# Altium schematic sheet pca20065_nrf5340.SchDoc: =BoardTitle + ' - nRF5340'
size A3; Organization: Nordic Semiconductor; DocumentNumber: 3; SheetNumber: 3; SheetTotal: 10; CompanyName: Nordic Semiconductor; DocumentSize: A3
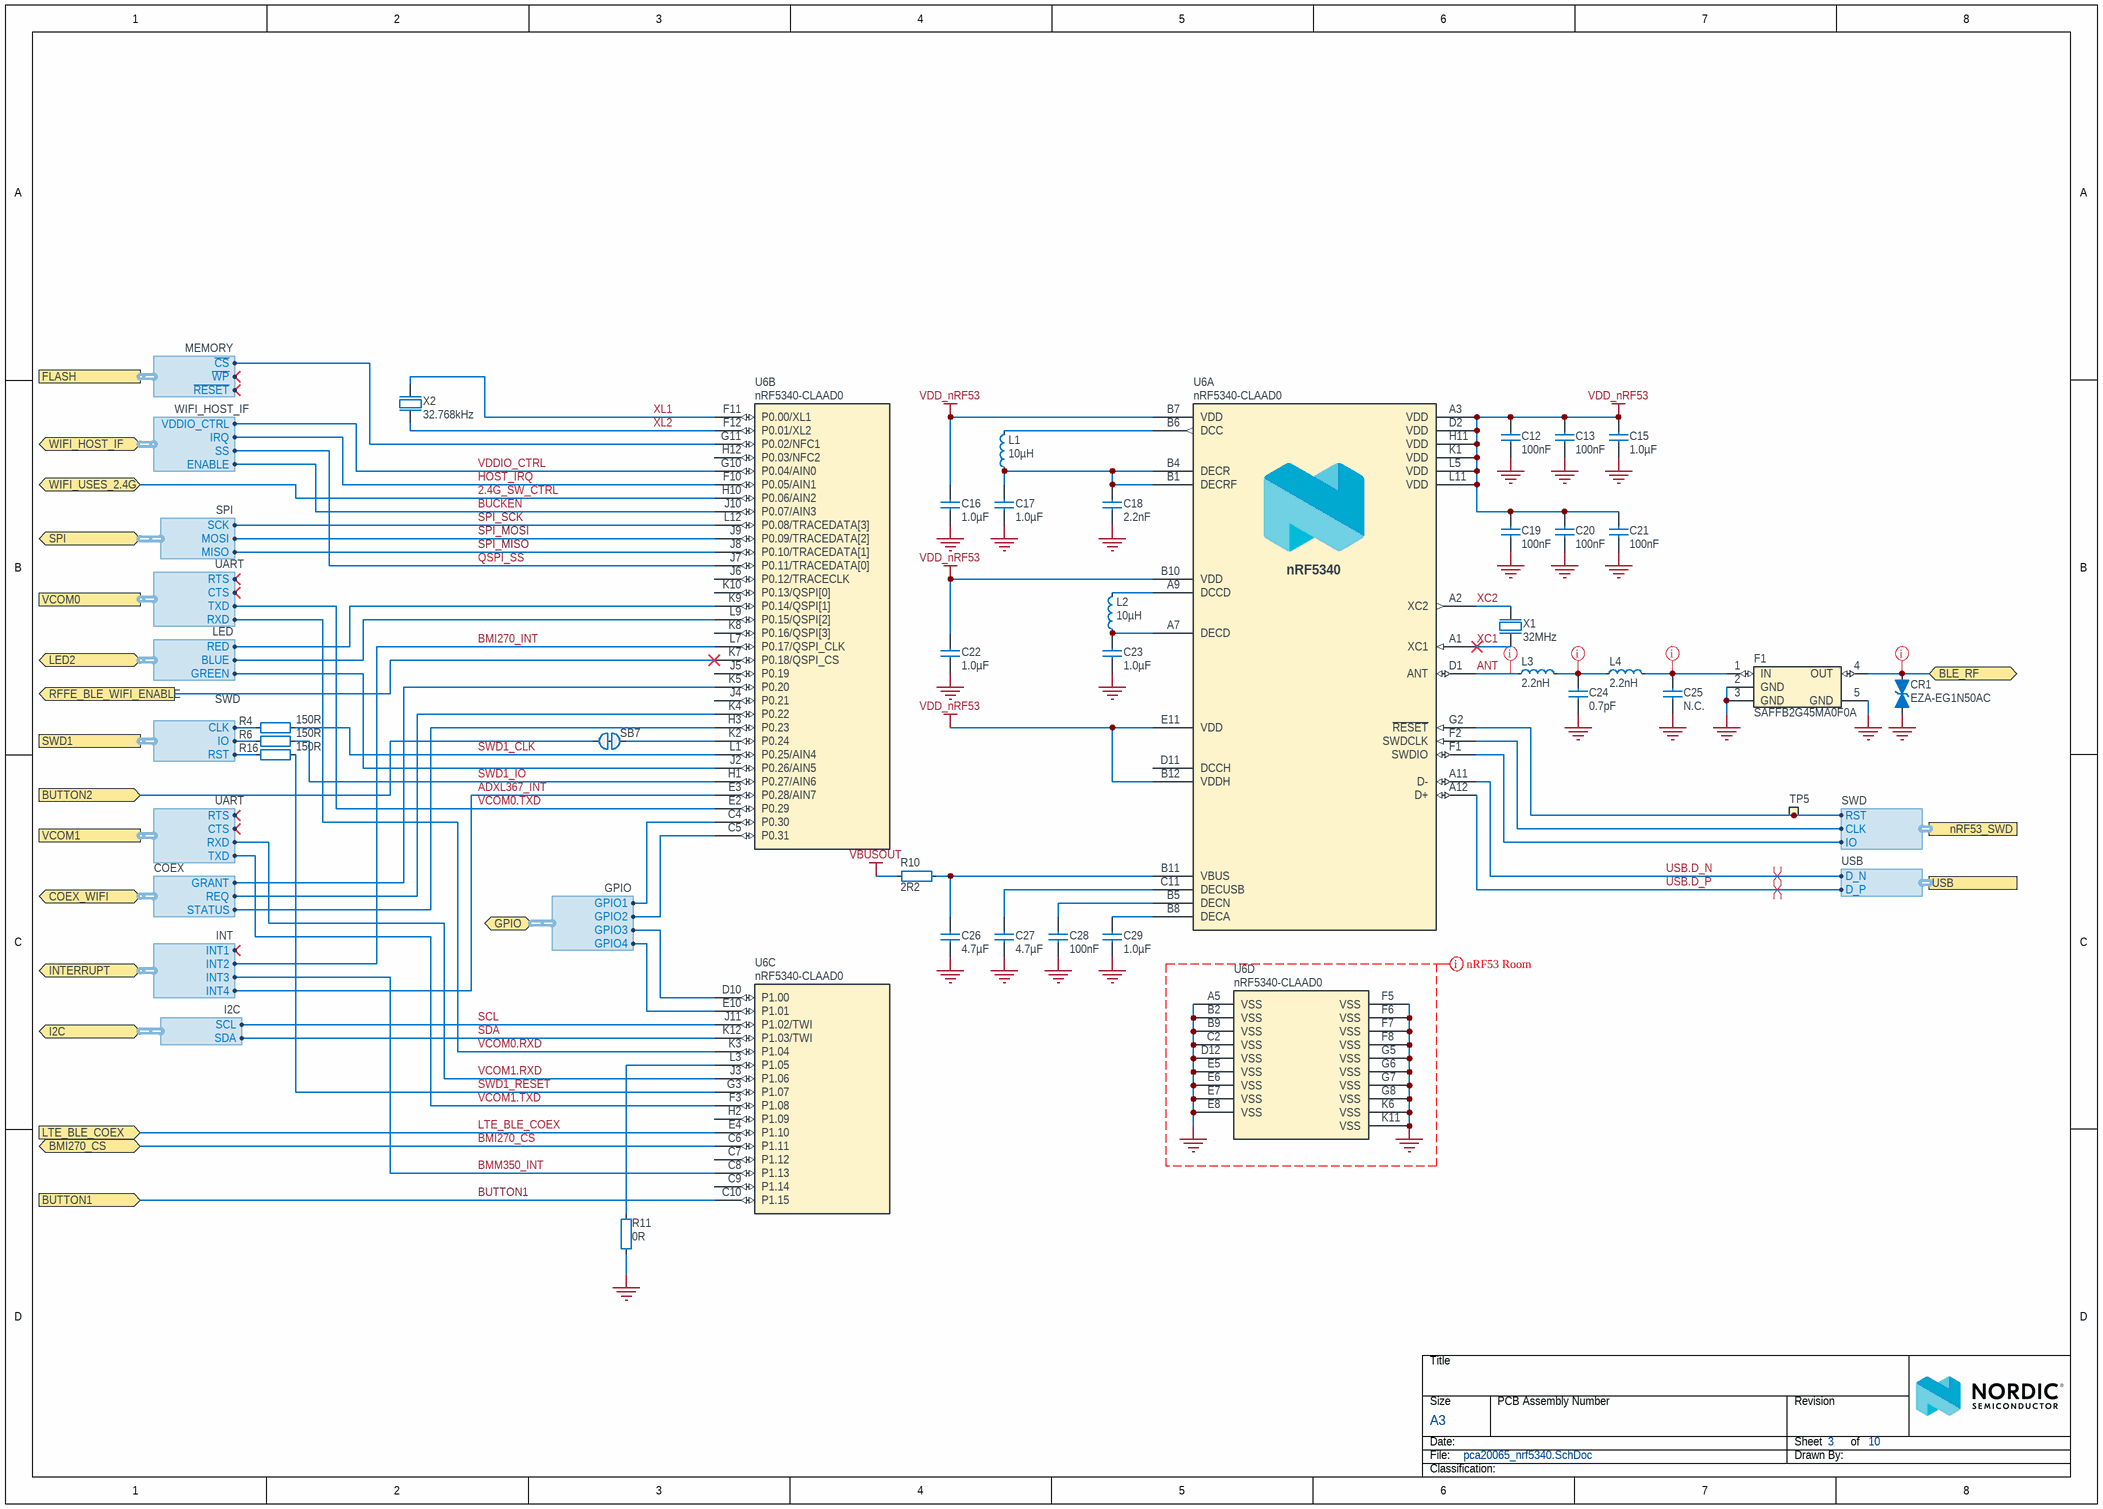
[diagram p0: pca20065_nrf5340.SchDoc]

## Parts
C12  100nF  [CAPC0603X03L_C]
C13  100nF  [CAPC0603X03L_C]
C15  1.0µF  [CAPC1005X04L]
C16  1.0µF  [CAPC1005X04L]
C17  1.0µF  [CAPC1005X04L]
C18  2.2nF  [CAPC0603X03L_C]
C19  100nF  [CAPC0603X03L_C]
C20  100nF  [CAPC0603X03L_C]
C21  100nF  [CAPC0603X03L_C]
C22  1.0µF  [CAPC1005X04L]
C23  1.0µF  [CAPC1005X04L]
C24  0.7pF  [CAPC0603X03L_C]
C25  N.C.  [CAPC0603X03L_C_NC]
C26  4.7µF  [CAPC1608X06L]
C27  4.7µF  [CAPC1608X06L]
C28  100nF  [CAPC0603X03L_C]
C29  1.0µF  [CAPC1005X04L]
CR1  EZA-EG1N50AC  [RESC0603X03L_C]
F1  SAFFB2G45MA0F0A  [SAFFB2G45MA0F0A]
L1  10µH  [INDC1608X06L]
L2  10µH  [INDC1608X06L]
L3  2.2nH  [INDC0603X03L_C]
L4  2.2nH  [INDC0603X03L_C]
R4  150R  [RESC0603X03L_C]
R6  150R  [RESC0603X03L_C]
R10  2R2  [RESC0603X03L_C]
R11  0R  [RESC0603X03L_C]
R16  150R  [RESC0603X03L_C]
SB7  Solderbridge  [Solderbridge_Shorted]  (value not drawn)  (net tie, no BOM)
TP5  Ø1.5mm,SMD  [TP_SMD_D1.5mm]  (value not drawn)  (no BOM)
U6  nRF5340-CLAAD0  [BGA95C35P12X11_437X397X50]  (parts A,B,C,D of 4)
X1  32MHz  [BT-XTAL_2016]
X2  32.768kHz  [XTAL_2012]

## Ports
BLE_RF (bidir), BMI270_CS (bidir), BUTTON1 (in), BUTTON2 (in), COEX_WIFI (bidir, harness COEX), FLASH (harness MEMORY), GPIO (bidir, harness GPIO), I2C (bidir, harness I2C), INTERRUPT (bidir, harness INT), LED2 (bidir, harness LED), LTE_BLE_COEX (in), nRF53_SWD (harness SWD), RFFE_BLE_WIFI_ENABLE (out), SPI (bidir, harness SPI), SWD1 (harness SWD), USB (harness USB), VCOM0 (harness UART), VCOM1 (harness UART), WIFI_HOST_IF (bidir, harness WIFI_HOST_IF), WIFI_USES_2.4G (bidir)

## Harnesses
I2C: SDA, SCL
SWD: IO, CLK, RST
USB: D_P, D_N
LED: BLUE, GREEN, RED
UART: RTS, CTS, RXD, TXD
WIFI_HOST_IF: SS, IRQ, ENABLE, VDDIO_CTRL
INT: INT2, INT3, INT1, INT4
COEX: STATUS, REQ, GRANT
SPI: MISO, MOSI, SCK
GPIO: GPIO2, GPIO3, GPIO1, GPIO4
MEMORY: ~{CS}, ~{WP}, ~{RESET}

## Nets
GND: C12.2 C13.2 C15.2 C16.2 C17.1 C18.2 C19.2 C20.2 C21.2 C22.1 C23.1 C24.1 C25.1 C26.2 C27.2 C28.2 C29.1 CR1.1 F1.2(GND) F1.3(GND) F1.5(GND) R11.1 U6.A5(VSS) U6.B2(VSS) U6.B9(VSS) U6.C2(VSS) U6.D12(VSS) U6.E5(VSS) U6.E6(VSS) U6.E7(VSS) U6.E8(VSS) U6.F5(VSS) U6.F6(VSS) U6.F7(VSS) U6.F8(VSS) U6.G5(VSS) U6.G6(VSS) U6.G7(VSS) U6.G8(VSS) U6.K6(VSS) U6.K11(VSS) X1.2(GND) X1.4(GND)
VBUSOUT: R10.1
VDD_nRF53: C12.1 C13.1 C15.1 C16.1 C19.1 C20.1 C21.1 C22.2 U6.A3(VDD) U6.B7(VDD) U6.B10(VDD) U6.B12(VDDH) U6.D2(VDD) U6.E11(VDD) U6.H11(VDD) U6.K1(VDD) U6.L5(VDD) U6.L11(VDD)
2.4G_SW_CTRL: U6.H10(P0.06/AIN2) ; port WIFI_USES_2.4G
ADXL367_INT: U6.E3(P0.28/AIN7) ; port INTERRUPT.INT4
ANT: L3.2 U6.D1(ANT)
BLE_RF: CR1.2 F1.4(OUT) ; port BLE_RF
BMI270_CS: U6.C6(P1.11) ; port BMI270_CS
BMI270_INT: U6.L7(P0.17/QSPI_CLK) ; port INTERRUPT.INT2
BMM350_INT: U6.C8(P1.13) ; port INTERRUPT.INT3
BUCKEN: U6.J10(P0.07/AIN3) ; port WIFI_HOST_IF.ENABLE
BUTTON1: U6.C10(P1.15) ; port BUTTON1
BUTTON2: SB7.2 ; port BUTTON2
HOST_IRQ: U6.F10(P0.05/AIN1) ; port WIFI_HOST_IF.IRQ
LTE_BLE_COEX: U6.E4(P1.10) ; port LTE_BLE_COEX
QSPI_SS: U6.J7(P0.11/TRACEDATA[0]) ; port WIFI_HOST_IF.SS
RFFE_BLE_WIFI_ENABLE: U6.K7(P0.18/QSPI_CS) ; port RFFE_BLE_WIFI_ENABLE
SCL: U6.J11(P1.02/TWI) ; port I2C.SCL
SDA: U6.K12(P1.03/TWI) ; port I2C.SDA
SWD1_CLK: R4.1 U6.L1(P0.25/AIN4)
SWD1_IO: R6.1 U6.H1(P0.27/AIN6)
SWD1_RESET: R16.1 U6.G3(P1.07)
USB.D_N: U6.A11(D-) ; port USB.D_N
USB.D_P: U6.A12(D+) ; port USB.D_P
VCOM0.RXD: U6.K3(P1.04) ; port VCOM0.RXD
VCOM0.TXD: U6.E2(P0.29) ; port VCOM0.TXD
VCOM1.RXD: U6.J3(P1.06) ; port VCOM1.RXD
VCOM1.TXD: U6.F3(P1.08) ; port VCOM1.TXD
VDDIO_CTRL: U6.G10(P0.04/AIN0) ; port WIFI_HOST_IF.VDDIO_CTRL
XC1: U6.A1(XC1) X1.1(inp)
XC2: U6.A2(XC2) X1.3(out)
XL1: U6.F11(P0.00/XL1) X2.1(inp)
XL2: U6.F12(P0.01/XL2) X2.2(out)
NetC17_2: C17.2 C18.1 L1.1 U6.B1(DECRF) U6.B4(DECR)
NetC23_2: C23.2 L2.1 U6.A7(DECD)
NetC24_2: C24.2 L3.1 L4.2
NetC25_2: C25.2 F1.1(IN) L4.1
NetC26_1: C26.1 R10.2 U6.B11(VBUS)
NetC27_1: C27.1 U6.C11(DECUSB)
NetC28_1: C28.1 U6.B5(DECN)
NetC29_2: C29.2 U6.B8(DECA)
NetL1_2: L1.2 U6.B6(DCC)
NetL2_2: L2.2 U6.A9(DCCD)
NetR4_2: R4.2 ; port SWD1.CLK
NetR6_2: R6.2 ; port SWD1.IO
NetR11_2: R11.2 U6.L3(P1.05)
NetR16_2: R16.2 ; port SWD1.RST
NetSB7_1: SB7.1 U6.K2(P0.24)
NetTP5_1: TP5.1 U6.G2(~{RESET}) ; port nRF53_SWD.RST
NetU6_C4: U6.C4(P0.30) ; port GPIO.GPIO1
NetU6_C5: U6.C5(P0.31) ; port GPIO.GPIO2
NetU6_D10: U6.D10(P1.00) ; port GPIO.GPIO3
NetU6_E10: U6.E10(P1.01) ; port GPIO.GPIO4
NetU6_F1: U6.F1(SWDIO) ; port nRF53_SWD.IO
NetU6_F2: U6.F2(SWDCLK) ; port nRF53_SWD.CLK
NetU6_G11: U6.G11(P0.02/NFC1) ; port FLASH.~{CS}
NetU6_H3: U6.H3(P0.23) ; port COEX_WIFI.STATUS
NetU6_J2: U6.J2(P0.26/AIN5) ; port LED2.GREEN
NetU6_J8: U6.J8(P0.10/TRACEDATA[1]) ; port SPI.MISO
NetU6_J9: U6.J9(P0.09/TRACEDATA[2]) ; port SPI.MOSI
NetU6_K4: U6.K4(P0.22) ; port COEX_WIFI.REQ
NetU6_K5: U6.K5(P0.20) ; port COEX_WIFI.GRANT
NetU6_K9: U6.K9(P0.14/QSPI[1]) ; port LED2.RED
NetU6_L9: U6.L9(P0.15/QSPI[2]) ; port LED2.BLUE
NetU6_L12: U6.L12(P0.08/TRACEDATA[3]) ; port SPI.SCK

Not connected (* = marked no-connect by the designer): U6 C7(P1.12) C9(P1.14) D11(DCCH) H2(P1.09) H12(P0.03/NFC2) J4(P0.21) J5(P0.19) J6(P0.12/TRACECLK) K8(P0.16/QSPI[3]) K10(P0.13/QSPI[0])

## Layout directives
differential pair: USB.D_N, USB.D_P
net class RF_BLE/WIFI: ANT, BLE_RF, NetC24_2, NetC25_2
CompClassName: nRF53: GND

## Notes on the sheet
- SPI_SCK
- SPI_MOSI
- SPI_MISO
- BUTTON1

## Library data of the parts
C12 C13 C19-C21 C28 = C0201-100n: Capacitor, X5R, ±10%; Part number IPS: 00000001248, 00000002505; Part number Norautron: 262071862; Part number NEMS: 100200078; Pad Count: 2; Artikkelnr Noca: N.A.; Note: 16V; Component Status: Active
C15-C17 C22 C23 C29 = C0402-1µ0-10V-X5R: Capacitor, Ceramic, X5R, ±10%, 10V; Manufacturer: N.A.; Part number NEMS: 100200482; Pad Count: 2; Component Status: Active
C18 = C0201-2n2: Capacitor, X7R, ±10%, 10V; Part number IPS: 00000001778; Part number Norautron: 26470002; Part number NEMS: 100200060; Pad Count: 2; Artikkelnr Noca: N.A.; Component Status: Active
C24 = C0201-0.7p-50V-C0G-GJM0335C1HR70WB01: Capacitor, Ceramic, C0G, ±0.05pF, 50V; Manufacturer: Murata; Manufacturer Part Number: GJM0335C1HR70WB01D; Part number NEMS: 100200011; Pad Count: 2; Artikkelnr Noca: N.A.; Component Status: Active
C25 = C0201-N.C.: Not mounted; Part number NEMS: 100200001; Assembly: Not mounted; Pad Count: 2; Artikkelnr Noca: N.A.; Note: Chip Cap; Component Status: Active
C26 = C0603-4µ7-10V-X7S: Capacitor, X7S, ±10%, 10V; Manufacturer: N.A.; Part number IPS: 00000001779; Part number NEMS: 100200351; Pad Count: 2; Artikkelnr Noca: 20030013; Component Status: Active
C27 = C0603-4µ7-6.3V-X7R: Capacitor, X7R, ±10%, 6.3V; Manufacturer: Samsung Electro-Mechanics America; Manufacturer Part Number: CL10B475KQ8NQNC; Part number IPS: 00000002541; Part number Norautron: N.A.; Part number NEMS: 100200350; Pad Count: 2; Artikkelnr Noca: 20039473; Component Status: Active
CR1 = EZA-EG1N50AC: ESD Suppressor, 30V, 0.04pF; Manufacturer: Panasonic; Part number IPS: 00000004437; Part number NEMS: 101300173; Note: N.A.; Pad Count: 2; Component Status: Active
F1 = SAFFB2G45MA0F0A: 2.4 GHz BPF; Manufacturer: Murata; Part number IPS: 00000001784, 80000001660; Part number NEMS: 100800023; Artikkelnr Noca: N.A.; Pad Count: 5; Component Status: Active
L1 L2 = L0603-10µ: Inductor, 80mA, ±10%; Manufacturer: Taiyo Yuden; Manufacturer Part Number: LBMF1608T100K; Part number IPS: 00000007794; Part number Norautron: N.A.; Part number NEMS: 100300078; Pad Count: 2; Artikkelnr Noca: 33029314; Note: LBMF1608T100K 10µH 80mA 0603; Component Status: Active
L3 L4 = L0201-2n2: Chip Inductor; Part number NEMS: 100300017; Pad Count: 2; Artikkelnr Noca: N.A.; Note: High frequency chip inductor ±5%; Component Status: Active
R4 R6 R16 = R0201-150: Resistor, ±1%, 0.05W; Manufacturer: N.A.; Part number IPS: 00000001420; Part number NEMS: 100100029; Note: Chip Res 1%; Pad Count: 2; Component Status: Active
R10 = R0201-2R2: Resistor, ±1%, 0.05W; Part number Norautron: 26470029; Part number NEMS: 100100006; Pad Count: 2; Artikkelnr Noca: N.A.; Note: Chip Res 1%; Component Status: Active
R11 = R0201-0R: Resistor, ±5%, 0.05W; Manufacturer: N.A.; Part number IPS: 00000003245; Part number NEMS: 100100001; Pad Count: 2; Note: Chip Res 5%; Component Status: Active
SB7 = Solderbridge Shorted: Shorted Solderbridge; Manufacturer: N.A.; Part number NEMS: 100500459; Component Status: Active; Pad Count: 2; System: Connector
TP5 = TP_SMD_Ø1.5MM: 1.5mm circular SMD testpad; Manufacturer: Nordic Semiconductor; Manufacturer Part Number: N.A.; Part number NEMS: 100500477; Pad Count: 1; Component Status: Active
U6 = nRF5340-CLAAD0: Multi-protocol Bluetooth Low Energy, IEEE 802.15.4, ANT and 2.4GHz proprietary system-on-chip; Manufacturer: Nordic Semiconductor; Part number NEMS: 102000319; Pad Count: 95; Note: N.A.; Component Status: Active
X1 = XTAL_SMD2016_32MHz_8pF_Kyocera_SA: XTAL SMD 2016, 32MHz, Cl=8pF, ±30ppm, -40°C ~ 105°C; Manufacturer Part Number: CX2016SA32000D0WRQG1; Part number NEMS: 101600100; Pad Count: 4; Artikkelnr Noca: N.A.; Note: XTAL SMD 32.000MHz; Component Status: Active
X2 = XTAL_SMD2012_32.768kHz_9pF_Golledge: XTAL SMD 2012, 32.768kHz, 9pF, ±20ppm; Manufacturer Part Number: MP07668; Part number Norautron: 26470047; Part number NEMS: 101600017; Pad Count: 2; Artikkelnr Noca: N.A.; Note: XTAL SMD 32.768kHz; Component Status: Active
